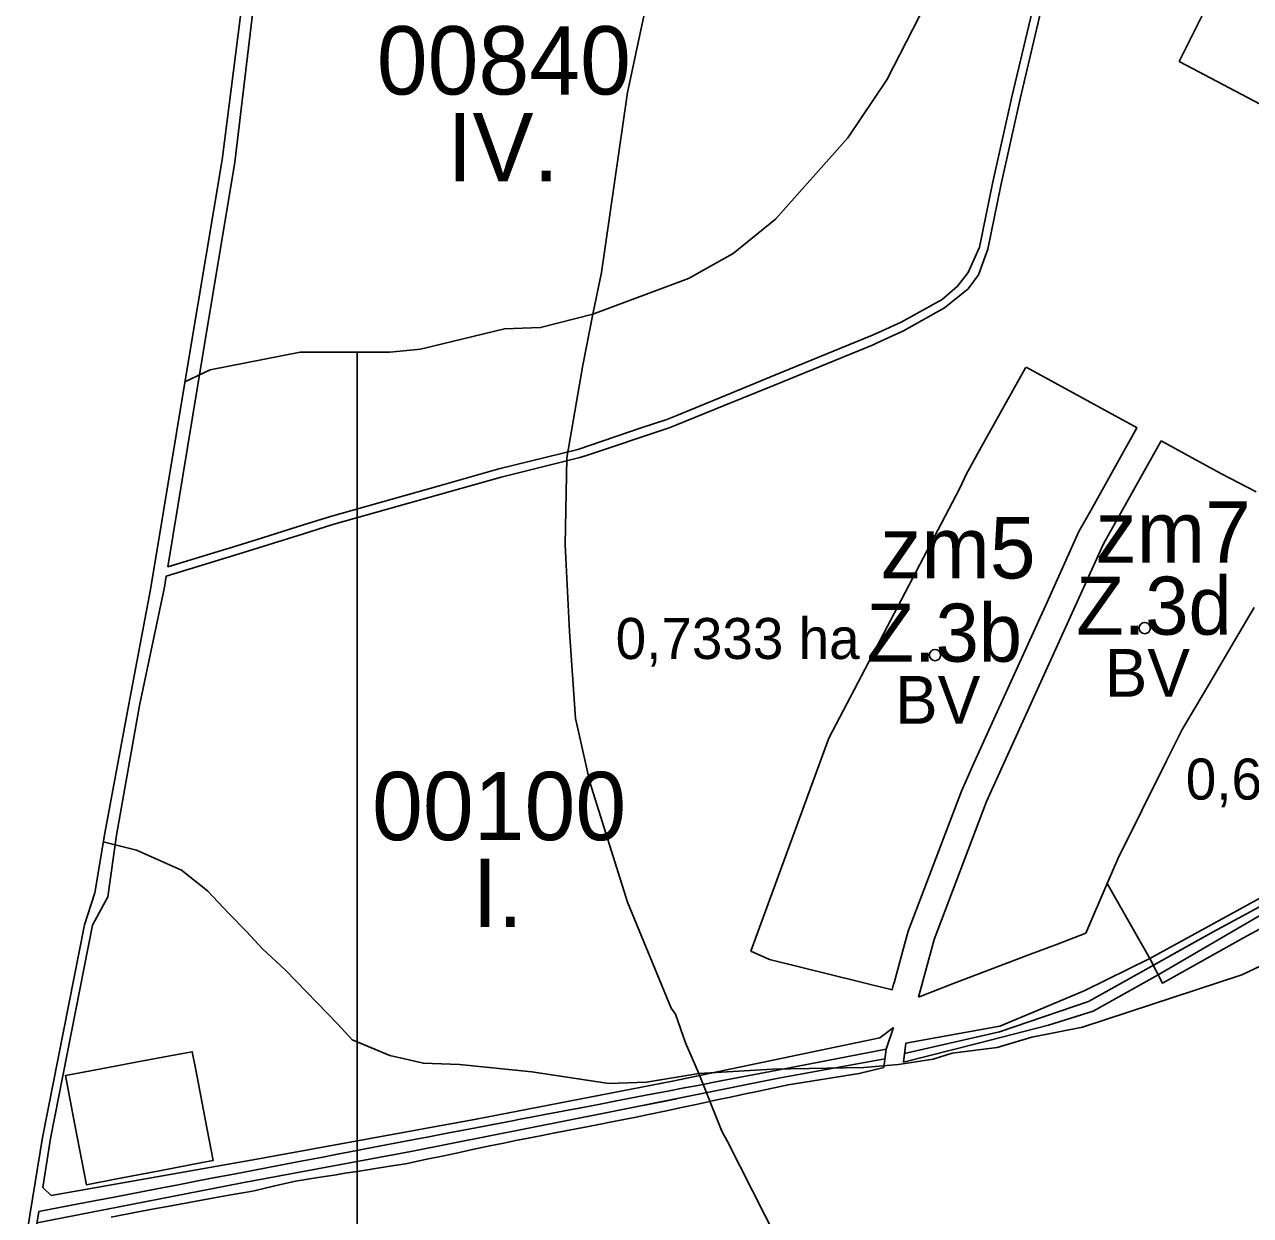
# Model space of a CAD drawing. Extents: x -555509 to -553014, y -1186753 to -1182560.
# Drawn here: x -555106.9 to -554748.1, y -1185549 to -1185200.4 of the extents above; entities that cross this region are included whole.
import ezdxf

# ---------------------------------------------------------------- set-up
doc = ezdxf.new("R2010")
doc.units = 0
for name, color, linetype in [('I_2_Leg_HV', 7, 'Continuous'), ('LEG_1_ZCU', 7, 'Continuous'), ('LEG_6_ZPF', 7, 'Continuous'), ('Level 29', 7, 'Continuous'), ('Level 4', 7, 'Continuous'), ('Level 46', 7, 'Continuous'), ('Level 52', 7, 'Continuous'), ('pěší_tr', 7, 'Continuous'), ('ram_HLV', 7, 'Continuous'), ('ZABOR_ke_zruseni', 7, 'Continuous'), ('zatrubnene_toky', 7, 'Continuous'), ('ZM_rozpiska_VYROK', 7, 'Continuous'), ('ZPF_I_TR_OCHRANY', 7, 'Continuous'), ('ZPF_zabor', 7, 'Continuous')]:
    doc.layers.add(name, color=color, linetype=linetype)

msp = doc.modelspace()

# ---------------------------------------------------------------- linework, layer by layer
at = {"layer": 'I_2_Leg_HV'}
msp.add_line((-554777.58, -1185473.79), (-554796.64, -1185483.19), dxfattribs=at)
for points in [[(-554698.96, -1185430.19), (-554711.78, -1185437.68), (-554777.58, -1185473.79)], [(-554775.16, -1185478.6), (-554743.55, -1185460.15), (-554715.8, -1185446.65)], [(-554794.19, -1185489.23), (-554775.19, -1185478.62), (-554775.16, -1185478.6)], [(-554796.64, -1185483.19), (-554810.27, -1185488.94), (-554821.46, -1185493.59), (-554849, -1185498.59), (-554849.65, -1185504.21)], [(-554849.65, -1185504.21), (-554827.71, -1185498.61), (-554807.22, -1185493.38), (-554794.19, -1185489.23)], [(-554854.76, -1185500.41), (-554888.64, -1185506.89), (-554903.1, -1185509.66), (-554910.38, -1185511.05), (-554913.87, -1185511.72), (-554918.61, -1185512.62), (-554923.5, -1185513.56), (-554927.12, -1185514.25), (-554931.17, -1185515.03), (-554934.15, -1185515.6), (-554937.97, -1185516.33), (-554941.01, -1185516.91), (-554944.04, -1185517.49), (-554947.31, -1185518.12), (-554950.92, -1185518.81), (-554954.69, -1185519.53), (-554958.66, -1185520.29), (-554962.31, -1185520.98), (-554963.61, -1185521.23), (-554969.77, -1185522.41), (-554974.79, -1185523.37), (-554979.51, -1185524.28), (-554983.18, -1185524.98), (-554988.59, -1185526.01), (-554993.42, -1185526.94), (-554998.99, -1185528), (-555005.14, -1185529.18), (-555008.64, -1185529.85), (-555012.2, -1185530.53), (-555014.8, -1185531.03), (-555020.1, -1185532.04), (-555026.57, -1185533.28), (-555045.61, -1185536.92), (-555051.08, -1185537.97), (-555055.68, -1185538.85), (-555061.91, -1185540.05), (-555068.16, -1185541.24), (-555080.68, -1185543.64), (-555085.98, -1185544.65), (-555091.07, -1185545.63), (-555096.18, -1185546.6), (-555102.7, -1185547.85)], [(-554909.87, -1185516.42), (-554904.33, -1185515.24), (-554900.28, -1185514.38), (-554895.57, -1185513.37), (-554893.89, -1185513.01), (-554883.45, -1185510.79), (-554862.64, -1185507.52), (-554855.48, -1185505.69), (-554854.76, -1185500.41)], [(-555081.55, -1185549.55), (-555074.12, -1185548.07), (-555069, -1185547.14), (-555063.99, -1185546.23), (-555051.91, -1185544), (-555046.49, -1185543.03), (-555041.83, -1185542.2), (-555039.67, -1185541.81), (-555034.04, -1185540.5), (-555027.57, -1185538.99), (-555020.99, -1185537.95), (-555015.72, -1185537.12), (-555013.13, -1185536.71), (-555009.54, -1185536.14), (-555006, -1185535.58), (-554999.96, -1185534.62), (-554995.45, -1185533.91), (-554994.49, -1185533.71), (-554989.62, -1185532.68), (-554984.24, -1185531.55), (-554980.5, -1185530.76), (-554975.77, -1185529.76), (-554970.72, -1185528.7), (-554966.63, -1185527.84), (-554962.77, -1185527.02), (-554962.1, -1185526.88), (-554957.47, -1185525.99), (-554955.45, -1185525.6), (-554951.71, -1185524.88), (-554948.05, -1185524.17), (-554944.96, -1185523.58), (-554941.91, -1185522.99), (-554938.86, -1185522.4), (-554935.03, -1185521.66), (-554932, -1185521.08), (-554927.94, -1185520.28), (-554924.32, -1185519.5), (-554919.49, -1185518.47), (-554914.65, -1185517.44), (-554909.87, -1185516.42)], [(-555102.7, -1185547.85), (-555103.67, -1185553.95)]]:
    msp.add_lwpolyline(points, dxfattribs=at)
at = {"layer": 'LEG_6_ZPF'}
for p, q in [((-554940.62, -1185285.25), (-554943.56, -1185300.13)), ((-554943.56, -1185300.13), (-554948.25, -1185327.25)), ((-554948.25, -1185327.25), (-554948.69, -1185352.75)), ((-554930.44, -1185457.38), (-554917.69, -1185488.38)), ((-554750.69, -1185478.63), (-554739.19, -1185473.12)), ((-554797.31, -1185493.88), (-554750.69, -1185478.63)), ((-554917.69, -1185488.38), (-554916.44, -1185490.13)), ((-554812.12, -1185496.88), (-554797.31, -1185493.88)), ((-554841, -1185503.25), (-554835.44, -1185501.5)), ((-554888, -1185506.25), (-554861.31, -1185505.75)), ((-554861.31, -1185505.75), (-554851.12, -1185504.88)), ((-554851.12, -1185504.88), (-554841, -1185503.25)), ((-554909.62, -1185507.5), (-554888, -1185506.25))]:
    msp.add_line(p, q, dxfattribs=at)
for points in [[(-554835.44, -1185179.25), (-554854.56, -1185216.62), (-554866, -1185233.62), (-554887.19, -1185257.38), (-554899.5, -1185267.5), (-554912.62, -1185274.75), (-554940.62, -1185285.25)], [(-554948.69, -1185352.75), (-554947.38, -1185378.13), (-554945.69, -1185403.62)], [(-554945.69, -1185403.62), (-554944.88, -1185407), (-554941.44, -1185422.25), (-554930.44, -1185457.38)], [(-554916.44, -1185490.13), (-554913.5, -1185498.5), (-554909.62, -1185507.5)], [(-554835.44, -1185501.5), (-554822.31, -1185499.88), (-554812.12, -1185496.88)]]:
    msp.add_lwpolyline(points, dxfattribs=at)
at = {"layer": 'Level 29'}
for points in [[(-554900.75, -1185116.5), (-554909.25, -1185140.75), (-554912.62, -1185147.5), (-554920.69, -1185174.63), (-554930.44, -1185220.38), (-554938.06, -1185273), (-554940.62, -1185285.25)], [(-554835.44, -1185179.25), (-554854.56, -1185216.62), (-554866, -1185233.62), (-554887.19, -1185257.38), (-554899.5, -1185267.5), (-554912.62, -1185274.75), (-554940.62, -1185285.25)], [(-554940.62, -1185285.25), (-554955.88, -1185289.13), (-554966.44, -1185289.5), (-554991.06, -1185295.5), (-555000, -1185296.38), (-555026.25, -1185296.38), (-555052.56, -1185301.5), (-555059.97, -1185305.01)], [(-554940.62, -1185285.25), (-554943.56, -1185300.13), (-554948.25, -1185327.25), (-554948.69, -1185352.75), (-554947.38, -1185378.13), (-554945.69, -1185403.62), (-554944.88, -1185407), (-554941.44, -1185422.25), (-554930.44, -1185457.38), (-554917.69, -1185488.38), (-554916.44, -1185490.13), (-554913.5, -1185498.5), (-554909.62, -1185507.5)], [(-555083.85, -1185439.63), (-555074.12, -1185442.13), (-555061, -1185448), (-555053.38, -1185454), (-555047.06, -1185460.75), (-555041.94, -1185465.88), (-555037.31, -1185471), (-555030.5, -1185477.25), (-555015.25, -1185493), (-555011, -1185497.62), (-555000, -1185502.25), (-554990.19, -1185504.5), (-554979.62, -1185504.88), (-554958.44, -1185507), (-554935.94, -1185510.38), (-554924.94, -1185510), (-554909.62, -1185507.5)], [(-554909.62, -1185507.5), (-554888, -1185506.25), (-554861.31, -1185505.75), (-554851.12, -1185504.88), (-554841, -1185503.25), (-554835.44, -1185501.5), (-554822.31, -1185499.88), (-554812.12, -1185496.88), (-554797.31, -1185493.88), (-554750.69, -1185478.63), (-554739.19, -1185473.12)], [(-554909.62, -1185507.5), (-554902.88, -1185524.38), (-554901.19, -1185527.38), (-554882.94, -1185563.38), (-554878.69, -1185573.62), (-554876.56, -1185577), (-554874.44, -1185582.12), (-554868.12, -1185594), (-554865.12, -1185600.75), (-554863, -1185604.13), (-554854.94, -1185619.38), (-554851.56, -1185624.5), (-554849, -1185629.62), (-554825.25, -1185668.63), (-554807.5, -1185699.12), (-554798.56, -1185721.13), (-554791.38, -1185750)]]:
    msp.add_lwpolyline(points, dxfattribs=at)
at = {"layer": 'Level 4'}
for centre in [(-554779.07, -1185377.11), (-554840.43, -1185385.02)]:
    msp.add_circle(centre, 1.64, dxfattribs=at)
at = {"layer": 'Level 52'}
for points in [[(-554747.05, -1185371.06), (-554752.81, -1185380.83), (-554760.45, -1185393.79), (-554768.14, -1185406.83), (-554772.69, -1185415.93), (-554786.97, -1185444.66), (-554790.07, -1185451.89), (-554783.65, -1185463.15), (-554777.58, -1185473.79), (-554773.94, -1185481.01), (-554750.17, -1185467.82), (-554741.93, -1185463.25)], [(-555092.18, -1185522.55), (-555088.82, -1185540.06), (-555079.9, -1185538.34), (-555067.4, -1185535.93), (-555054.94, -1185533.53), (-555051.7, -1185532.91), (-555053.44, -1185523.9), (-555056.79, -1185506.46), (-555057.82, -1185501.14), (-555062.21, -1185501.96), (-555074.79, -1185504.31), (-555079.88, -1185505.26), (-555084.52, -1185506.13), (-555089.21, -1185507), (-555094.96, -1185508.08), (-555092.18, -1185522.55)]]:
    msp.add_lwpolyline(points, dxfattribs=at)
at = {"layer": 'pěší_tr'}
for points in [[(-555038.22, -1185140.93), (-555040.43, -1185171.71), (-555049.1, -1185240.01), (-555058.64, -1185297.02), (-555070.07, -1185365.86), (-555076.4, -1185399.4), (-555083.43, -1185437.16), (-555086.38, -1185454.6), (-555089.38, -1185463.99), (-555101.61, -1185526.2), (-555105.26, -1185548.34), (-555106.28, -1185554.52), (-555106.91, -1185558.36)], [(-555054.79, -1185297.6), (-555045.36, -1185240.74), (-555037.15, -1185172.01), (-555035.33, -1185141.55)], [(-555101.59, -1185540.83), (-555099.34, -1185526.52), (-555086.97, -1185464.05), (-555082.53, -1185455.8), (-555080.03, -1185437.72), (-555073.3, -1185399.76), (-555065.94, -1185365.09), (-555065.41, -1185361.92), (-555063.18, -1185361.24), (-555044.07, -1185355.4), (-555025.58, -1185349.62), (-555016.69, -1185346.84), (-554985.5, -1185338.03), (-554967.39, -1185332.91), (-554944.37, -1185327.23), (-554942.44, -1185326.58), (-554918.26, -1185318.5), (-554916.33, -1185317.72), (-554902.16, -1185311.95), (-554887.45, -1185305.97), (-554858.52, -1185294.2), (-554857.36, -1185293.66), (-554849.71, -1185290.09), (-554837.67, -1185283.42), (-554830.73, -1185277.79), (-554827.75, -1185273.76), (-554824.98, -1185266.19), (-554821.19, -1185247.57), (-554815.55, -1185222.19), (-554808.68, -1185193.09)], [(-554810.95, -1185192.05), (-554817.98, -1185221.63), (-554823.63, -1185247), (-554827.41, -1185265.63), (-554830.77, -1185273.06), (-554833.85, -1185277.07), (-554838.37, -1185280.92), (-554846.66, -1185285.51), (-554850.4, -1185287.59), (-554857.04, -1185290.6), (-554859.24, -1185291.6), (-554887.1, -1185303.03), (-554901.81, -1185309.08), (-554916.01, -1185314.9), (-554918.93, -1185316.1), (-554926.41, -1185318.46), (-554945.03, -1185324.82), (-554968.06, -1185330.5), (-554985.17, -1185335.34), (-555017.36, -1185344.44), (-555025.25, -1185346.9), (-555037.24, -1185350.65), (-555044.74, -1185352.99), (-555050.2, -1185354.66), (-555064.96, -1185359.17), (-555054.79, -1185297.6)], [(-554852.65, -1185494.03), (-554856.6, -1185497.07), (-554917.32, -1185509.78), (-554974.74, -1185520.88), (-555038.97, -1185532.52), (-555099.07, -1185543.16), (-555101.59, -1185540.83)], [(-554854.76, -1185500.41), (-554852.65, -1185494.03)], [(-555103.67, -1185553.95), (-555102.7, -1185547.85), (-555096.18, -1185546.6), (-555091.07, -1185545.63), (-555085.98, -1185544.65), (-555080.68, -1185543.64), (-555068.16, -1185541.24), (-555061.91, -1185540.05), (-555055.68, -1185538.85), (-555051.08, -1185537.97), (-555045.61, -1185536.92), (-555026.57, -1185533.28), (-555020.1, -1185532.04), (-555014.8, -1185531.03), (-555012.2, -1185530.53), (-555008.64, -1185529.85), (-555005.14, -1185529.18), (-554998.99, -1185528), (-554993.42, -1185526.94), (-554988.59, -1185526.01), (-554983.18, -1185524.98), (-554979.51, -1185524.28), (-554974.79, -1185523.37), (-554969.77, -1185522.41), (-554968.71, -1185522.21), (-554963.61, -1185521.23), (-554962.31, -1185520.98), (-554958.66, -1185520.29), (-554954.69, -1185519.53), (-554950.92, -1185518.81), (-554947.31, -1185518.12), (-554944.04, -1185517.49), (-554941.01, -1185516.91), (-554937.97, -1185516.33), (-554934.15, -1185515.6), (-554931.17, -1185515.03), (-554927.12, -1185514.25), (-554923.5, -1185513.56), (-554918.61, -1185512.62), (-554913.87, -1185511.72), (-554910.38, -1185511.05), (-554903.1, -1185509.66), (-554888.64, -1185506.89), (-554854.76, -1185500.41)]]:
    msp.add_lwpolyline(points, dxfattribs=at)
at = {"layer": 'ZABOR_ke_zruseni'}
for p, q in [((-554769.05, -1185211.23), (-554768.86, -1185211.34)), ((-554768.86, -1185211.34), (-554736.6, -1185228.38))]:
    msp.add_line(p, q, dxfattribs=at)
msp.add_lwpolyline([(-554753.06, -1185179.2), (-554755.68, -1185184.45), (-554769.05, -1185211.23)], dxfattribs=at)
at = {"layer": 'zatrubnene_toky'}
for points in [[(-554445.49, -1185223.21), (-554454.96, -1185233.2), (-554483.05, -1185256.78), (-554490.83, -1185263.4), (-554522.76, -1185291.29), (-554542.15, -1185304.6), (-554577.54, -1185334.32), (-554633.5, -1185381.96), (-554668, -1185411.5), (-554681.46, -1185422.71), (-554708.78, -1185438.76), (-554758.85, -1185465.95), (-554795.57, -1185486.43), (-554821.6, -1185495.33), (-554849.36, -1185501.68)], [(-554771.8, -1185473.17), (-554760.97, -1185467.13)], [(-554855.15, -1185503.23), (-554886.23, -1185508.85), (-554936.81, -1185519.03), (-554993.89, -1185530.31), (-555043.24, -1185539.52), (-555103.24, -1185551.24)], [(-554925.84, -1185516.87), (-554916.03, -1185514.92)]]:
    msp.add_lwpolyline(points, dxfattribs=at)
at = {"layer": 'ZPF_I_TR_OCHRANY'}
for p, q in [((-555009.53, -1185296.38), (-555009.53, -1185498.24)), ((-555000, -1185502.25), (-555009.53, -1185498.24)), ((-555009.53, -1185498.24), (-555009.53, -1185807.07)), ((-554990.19, -1185504.5), (-555000, -1185502.25)), ((-554979.62, -1185504.88), (-554990.19, -1185504.5)), ((-554909.62, -1185507.5), (-554924.94, -1185510)), ((-554924.94, -1185510), (-554935.94, -1185510.38))]:
    msp.add_line(p, q, dxfattribs=at)
for points in [[(-554940.62, -1185285.25), (-554955.88, -1185289.13), (-554966.44, -1185289.5), (-554991.06, -1185295.5), (-555000, -1185296.38), (-555009.53, -1185296.38)], [(-554909.62, -1185507.5), (-554913.5, -1185498.5), (-554916.44, -1185490.13), (-554917.69, -1185488.38), (-554930.44, -1185457.38), (-554941.44, -1185422.25), (-554944.88, -1185407), (-554945.69, -1185403.62), (-554947.38, -1185378.13), (-554948.69, -1185352.75), (-554948.25, -1185327.25), (-554943.56, -1185300.13), (-554940.62, -1185285.25)], [(-554739.19, -1185473.12), (-554750.69, -1185478.63), (-554797.31, -1185493.88), (-554812.12, -1185496.88), (-554822.31, -1185499.88), (-554835.44, -1185501.5), (-554841, -1185503.25), (-554851.12, -1185504.88), (-554861.31, -1185505.75), (-554888, -1185506.25), (-554909.62, -1185507.5)], [(-555009.53, -1185498.24), (-555000, -1185502.25), (-554990.19, -1185504.5), (-554979.62, -1185504.88), (-554958.44, -1185507), (-554935.94, -1185510.38), (-554924.94, -1185510), (-554909.62, -1185507.5)], [(-554935.94, -1185510.38), (-554958.44, -1185507), (-554979.62, -1185504.88)], [(-554791.38, -1185750), (-554798.56, -1185721.13), (-554807.5, -1185699.12), (-554825.25, -1185668.63), (-554849, -1185629.62), (-554851.56, -1185624.5), (-554854.94, -1185619.38), (-554863, -1185604.13), (-554865.12, -1185600.75), (-554868.12, -1185594), (-554874.44, -1185582.12), (-554876.56, -1185577), (-554878.69, -1185573.62), (-554882.94, -1185563.38), (-554901.19, -1185527.38), (-554902.88, -1185524.38), (-554909.62, -1185507.5)], [(-554909.62, -1185507.5), (-554902.88, -1185524.38), (-554901.19, -1185527.38), (-554882.94, -1185563.38), (-554878.69, -1185573.62), (-554876.56, -1185577), (-554874.44, -1185582.12)]]:
    msp.add_lwpolyline(points, dxfattribs=at)
at = {"layer": 'ZPF_zabor'}
for p, q in [((-554813.94, -1185300.96), (-554826.92, -1185324.2)), ((-554813.83, -1185300.75), (-554813.94, -1185300.96)), ((-554781.34, -1185318.48), (-554813.83, -1185300.75)), ((-554794.88, -1185342.72), (-554781.36, -1185318.51)), ((-554781.36, -1185318.51), (-554781.34, -1185318.48)), ((-554774.32, -1185322.31), (-554791.18, -1185352.5)), ((-554765.45, -1185327.15), (-554774.32, -1185322.31)), ((-554756.64, -1185331.95), (-554765.45, -1185327.15)), ((-554746.53, -1185337.24), (-554756.64, -1185331.95)), ((-554833.18, -1185336.15), (-554871.53, -1185409.38)), ((-554798.33, -1185348.89), (-554794.88, -1185342.72)), ((-554807.68, -1185369.52), (-554798.33, -1185348.89)), ((-554791.18, -1185352.5), (-554825.35, -1185427.87)), ((-554823.22, -1185403.79), (-554807.68, -1185369.52)), ((-554752.81, -1185380.83), (-554747.05, -1185371.06)), ((-554760.45, -1185393.79), (-554752.81, -1185380.83)), ((-554768.14, -1185406.83), (-554760.45, -1185393.79)), ((-554829.45, -1185417.54), (-554823.22, -1185403.79)), ((-554772.69, -1185415.93), (-554768.14, -1185406.83)), ((-554871.53, -1185409.38), (-554894.36, -1185471.66)), ((-554786.97, -1185444.66), (-554772.69, -1185415.93)), ((-554848.3, -1185465.81), (-554834.79, -1185430.19)), ((-554825.35, -1185427.87), (-554840.69, -1185468.29)), ((-554790.07, -1185451.89), (-554786.97, -1185444.66)), ((-554796.32, -1185466.44), (-554790.07, -1185451.89)), ((-554790.07, -1185451.89), (-554790.07, -1185451.89)), ((-554849.67, -1185470.78), (-554848.3, -1185465.81)), ((-554804.61, -1185469.6), (-554796.32, -1185466.44)), ((-554840.69, -1185468.29), (-554845.3, -1185485.1)), ((-554812.49, -1185472.6), (-554804.61, -1185469.6)), ((-554894.36, -1185471.66), (-554888.92, -1185474.12)), ((-554852.46, -1185480.97), (-554849.67, -1185470.78)), ((-554835.3, -1185481.29), (-554812.49, -1185472.6)), ((-554888.92, -1185474.12), (-554853.01, -1185482.98)), ((-554853.01, -1185482.98), (-554852.47, -1185480.98)), ((-554852.47, -1185480.98), (-554852.46, -1185480.97)), ((-554845.3, -1185485.1), (-554835.3, -1185481.29))]:
    msp.add_line(p, q, dxfattribs=at)
for points in [[(-554826.92, -1185324.2), (-554831.39, -1185332.2), (-554833.18, -1185336.15)], [(-554834.79, -1185430.19), (-554832.74, -1185424.8), (-554829.45, -1185417.54)]]:
    msp.add_lwpolyline(points, dxfattribs=at)

# ---------------------------------------------------------------- texts
at = {"layer": 'LEG_1_ZCU'}
for s, p in [('0,7333 ha', (-554933.92, -1185386.16)), ('0,6959 ha', (-554767.08, -1185427.31))]:
    msp.add_text(s, height=12, dxfattribs=at).set_placement(p)
at = {"layer": 'Level 29'}
for s, p in [('00840', (-555003.82, -1185220.93)), ('IV.', (-554983.24, -1185246.38)), ('00100', (-555005.2, -1185439.19)), ('I.', (-554975.89, -1185464.65))]:
    msp.add_text(s, height=20, dxfattribs=at).set_placement(p)
at = {"layer": 'Level 46'}
for s, p in [('Z.3d', (-554799.13, -1185379.05)), ('Z.3b', (-554860.49, -1185386.96))]:
    msp.add_text(s, height=17, dxfattribs=at).set_placement(p)
at = {"layer": 'ram_HLV'}
for p in [(-554790.82, -1185397.22), (-554852.18, -1185405.13)]:
    msp.add_text('BV', height=14, dxfattribs=at).set_placement(p)
at = {"layer": 'ZM_rozpiska_VYROK'}
for s, p in [('zm7', (-554793.5, -1185357.97)), ('zm5', (-554856.5, -1185362.59))]:
    msp.add_text(s, height=18, dxfattribs=at).set_placement(p)

doc.saveas('drawing.dxf')
